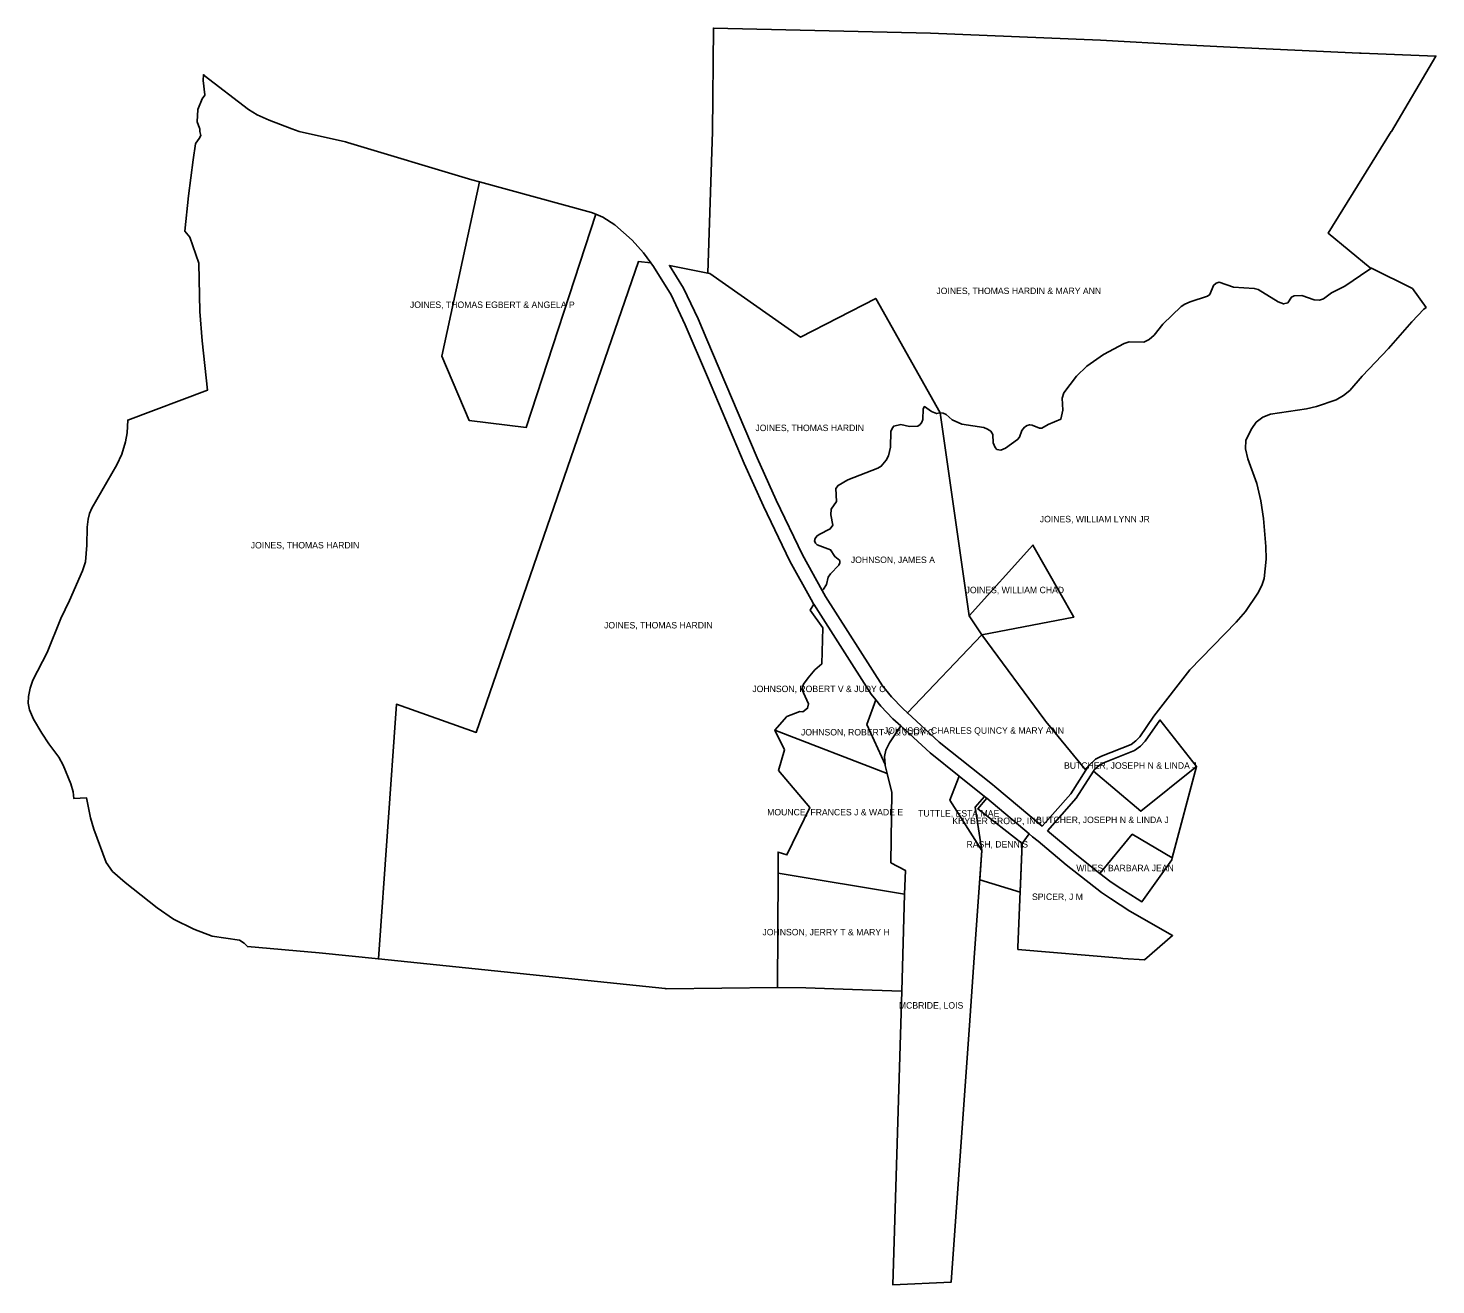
# Model space of a CAD drawing. Extents: x 1390770 to 1396754, y 955095 to 960439.
import ezdxf

# ---------------------------------------------------------------- set-up
doc = ezdxf.new("R2010")
doc.units = 0
doc.layers.add('WILKES_2010PARCELS', color=7, linetype='Continuous')

msp = doc.modelspace()

# ---------------------------------------------------------------- linework, layer by layer
at = {"layer": 'WILKES_2010PARCELS'}
for points in [[(1393678.875, 959999.75), (1393683, 960439.3125), (1394605.75, 960418.125), (1395328, 960388.125), (1395680.375, 960368.9375), (1395879.375, 960358.125), (1396429.75, 960332.8125), (1396436, 960332.5), (1396753.625, 960320.4375), (1396564.5, 960000)], [(1391500.5, 960000), (1391500.5, 960011.5), (1391498, 960014.4375), (1391489.125, 960040.4375), (1391491.5, 960092.8125), (1391509.5, 960139.25), (1391521.125, 960154.4375), (1391520.875, 960156.1875), (1391513.5, 960216.5), (1391515.375, 960241.75), (1391518.875, 960238.3125), (1391707.125, 960093.0625), (1391743.75, 960071), (1391795, 960047.875), (1391890.75, 960011.375), (1391921.5, 960000)], [(1391921.5, 960000), (1392119.375, 959955.625), (1392128.125, 959953), (1392656.125, 959794), (1392688.375, 959785.1875), (1392529.25, 959044.125), (1392645, 958770.1875), (1392886.875, 958740.9375), (1393182.5, 959647.8125), (1393212.75, 959635.4375), (1393264.375, 959602.3125), (1393337.625, 959537.75), (1393385.375, 959483.3125), (1393417.125, 959441), (1393364.5, 959446.25), (1392674.75, 957444.0625), (1392335.875, 957564.125), (1392259, 956480.9375), (1392007.75, 956507), (1391702.5, 956533.875), (1391688.875, 956548.25), (1391667.875, 956560.5), (1391553, 956577.25), (1391475.125, 956607.875), (1391388.5, 956650.5625), (1391318, 956699), (1391182.5, 956805.625), (1391128.75, 956852.875), (1391102.125, 956891.125), (1391049.875, 957032.375), (1391035.625, 957080.875), (1391018.25, 957166), (1390964.75, 957163.25), (1390961.5, 957191.125), (1390952.125, 957225.6875), (1390918.875, 957304.5625), (1390900, 957339.625), (1390858.5, 957396.0625), (1390828.125, 957440.625), (1390793.125, 957501.3125), (1390776, 957539.875), (1390770.25, 957568.5625), (1390771.875, 957597.375), (1390778.875, 957631.9375), (1390789.75, 957666.1875), (1390850.625, 957783.9375), (1390909, 957928.1875), (1390946.625, 958005.6875), (1391001.125, 958132.0625), (1391013.5, 958169.75), (1391019.625, 958241.25), (1391021.75, 958316.6875), (1391024.75, 958351.75), (1391031.25, 958375.25), (1391040.625, 958397.75), (1391147.625, 958582.875), (1391168.875, 958627.8125), (1391184.5, 958679.5), (1391190.625, 958718.25), (1391193.375, 958772.6875), (1391532, 958899.375), (1391510.125, 959109.9375), (1391500.125, 959234.0625), (1391496.125, 959439.875), (1391457.375, 959550), (1391436.5, 959575.625), (1391451.375, 959725.75), (1391472, 959879.8125), (1391481, 959947.5625), (1391482.875, 959950), (1391497.75, 959969.9375), (1391503.75, 959982.75), (1391500.5, 960000)], [(1396564.375, 960000), (1396295.25, 959568.0625), (1396475, 959420.375), (1396479.875, 959418.6875), (1396468.875, 959411.1875), (1396367.375, 959342.25), (1396310.5, 959314.1875), (1396276.75, 959288.5625), (1396259, 959281.8125), (1396236.625, 959283.5), (1396184.125, 959302.1875), (1396150.75, 959301.125), (1396140.125, 959295.4375), (1396124.875, 959271.8125), (1396106.375, 959266.3125), (1396083.75, 959275.875), (1395998.625, 959327.8125), (1395981.5, 959332.25), (1395893.375, 959337.125), (1395832.875, 959358.9375), (1395819.875, 959354.4375), (1395808.875, 959345.4375), (1395792.875, 959306.625), (1395783.75, 959299.25), (1395710, 959275.375), (1395686.75, 959266.1875), (1395671.25, 959256), (1395593.5, 959179.875), (1395556.25, 959134.125), (1395534.625, 959114.5625), (1395513.125, 959104.1875), (1395450, 959105.375), (1395429.375, 959098.0625), (1395341.5, 959051.4375), (1395269.625, 959001.3125), (1395226.25, 958959.75), (1395172.125, 958887.9375), (1395165.375, 958865.3125), (1395168.25, 958814.4375), (1395160.25, 958776.9375), (1395106.25, 958754.4375), (1395079, 958737.625), (1395068.375, 958737.5625), (1395038.25, 958750.4375), (1395027.125, 958752.4375), (1395015.875, 958749.625), (1395005.625, 958742.9375), (1394994.5, 958728.125), (1394983.5, 958699.25), (1394976.125, 958689.9375), (1394924.5, 958653.6875), (1394905.125, 958644.25), (1394887.75, 958647.6875), (1394879.875, 958656.25), (1394871.75, 958675.625), (1394870.5, 958711.3125), (1394862.125, 958725), (1394848.625, 958734.5625), (1394832.5, 958740.875), (1394738.875, 958754.875), (1394698.25, 958774.0625), (1394671.875, 958796.6875), (1394659.625, 958802.0625), (1394646.5, 958803.25), (1394372.75, 959290.1875), (1394052.75, 959125.375), (1393667.75, 959396.1875), (1393659.625, 959397.8125), (1393678.875, 960000)]]:
    msp.add_lwpolyline(points, dxfattribs=at)
for points in [[(1392529.25, 959044.125), (1392688.375, 959785.1875), (1393164.625, 959655.125), (1393182.5, 959647.8125), (1392886.875, 958740.9375), (1392645, 958770.1875)], [(1392674.75, 957444.0625), (1393364.5, 959446.25), (1393417.125, 959441), (1393428.25, 959426.125), (1393503.125, 959305.375), (1393563.25, 959178.25), (1393657.25, 958956.9375), (1393814, 958587.75), (1393895.375, 958406.125), (1394008, 958172.4375), (1394098.875, 958009.0625), (1394108.5, 957991.625), (1394109.875, 957989.375), (1394094.5, 957963.5625), (1394148, 957889.5625), (1394143.25, 957735.5625), (1394114, 957710.375), (1394085.25, 957676), (1394066.5, 957648.8125), (1394058.5, 957628), (1394086.875, 957565.625), (1394083.25, 957547.1875), (1394063.25, 957531.1875), (1394049.625, 957533.1875), (1393995.25, 957512), (1393944, 957454.4375), (1393984.875, 957370.8125), (1393960, 957282.0625), (1394092.5, 957125.25), (1393995.625, 956923.25), (1393958, 956935.25), (1393957.5, 956845.75), (1393954.875, 956358.9375), (1393482.5, 956354.1875), (1393478.25, 956354.625), (1392259, 956480.9375), (1392335.875, 957564.125)], [(1394145.5, 958048.5), (1394061.25, 958200.0625), (1393949.875, 958431.375), (1393869, 958611.75), (1393655.25, 959115.1875), (1393618, 959202.875), (1393555.875, 959334.125), (1393496.125, 959430.3125), (1393659.625, 959397.8125), (1393667.75, 959396.1875), (1394052.75, 959125.375), (1394372.75, 959290.1875), (1394646.5, 958803.25), (1394631.625, 958800.0625), (1394610, 958808.75), (1394579.5, 958829.6875), (1394574.625, 958820.5), (1394572.375, 958775.25), (1394569.125, 958763.0625), (1394561.625, 958753.375), (1394551.625, 958746.875), (1394516.25, 958745.4375), (1394479.25, 958753.0625), (1394449.625, 958746.875), (1394444.25, 958740.125), (1394437.625, 958724.0625), (1394436, 958657.25), (1394427.625, 958620.4375), (1394417.5, 958602.5625), (1394396.375, 958576.375), (1394382.375, 958567.375), (1394254.375, 958518), (1394212.5, 958494.5625), (1394203.5, 958481.5625), (1394206.375, 958425.9375), (1394184, 958393.125), (1394182.375, 958369.875), (1394190.375, 958325.125), (1394179.375, 958309.375), (1394132.75, 958285.875), (1394122.375, 958278.9375), (1394115, 958269.5), (1394112.75, 958259.125), (1394116.375, 958249.625), (1394124, 958241.4375), (1394180.75, 958220.3125), (1394198.375, 958191.875), (1394219.75, 958175.125), (1394219.875, 958166.125), (1394215.5, 958155.625), (1394181.25, 958118.875), (1394171, 958103.875), (1394163.5, 958073.6875), (1394150.75, 958053.4375)], [(1394769.5, 957939.6875), (1394646.5, 958803.25), (1394659.625, 958802.0625), (1394671.875, 958796.6875), (1394698.25, 958774.0625), (1394738.875, 958754.875), (1394832.5, 958740.875), (1394848.625, 958734.5625), (1394862.125, 958725), (1394870.5, 958711.3125), (1394871.75, 958675.625), (1394879.875, 958656.25), (1394887.75, 958647.6875), (1394905.125, 958644.25), (1394924.5, 958653.6875), (1394976.125, 958689.9375), (1394983.5, 958699.25), (1394994.5, 958728.125), (1395005.625, 958742.9375), (1395015.875, 958749.625), (1395027.125, 958752.4375), (1395038.25, 958750.4375), (1395068.375, 958737.5625), (1395079, 958737.625), (1395106.25, 958754.4375), (1395160.25, 958776.9375), (1395168.25, 958814.4375), (1395165.375, 958865.3125), (1395172.125, 958887.9375), (1395226.25, 958959.75), (1395269.625, 959001.3125), (1395341.5, 959051.4375), (1395429.375, 959098.0625), (1395450, 959105.375), (1395513.125, 959104.1875), (1395534.625, 959114.5625), (1395556.25, 959134.125), (1395593.5, 959179.875), (1395671.25, 959256), (1395686.75, 959266.1875), (1395710, 959275.375), (1395783.75, 959299.25), (1395792.875, 959306.625), (1395808.875, 959345.4375), (1395819.875, 959354.4375), (1395832.875, 959358.9375), (1395893.375, 959337.125), (1395981.5, 959332.25), (1395998.625, 959327.8125), (1396083.75, 959275.875), (1396106.375, 959266.3125), (1396124.875, 959271.8125), (1396140.125, 959295.4375), (1396150.75, 959301.125), (1396184.125, 959302.1875), (1396236.625, 959283.5), (1396259, 959281.8125), (1396276.75, 959288.5625), (1396310.5, 959314.1875), (1396367.375, 959342.25), (1396468.875, 959411.1875), (1396479.875, 959418.6875), (1396654.125, 959332.3125), (1396712.125, 959251.4375), (1396703, 959244.6875), (1396651.5, 959190.6875), (1396552.375, 959076.875), (1396439.875, 958959.25), (1396387.5, 958898.75), (1396361.625, 958876.8125), (1396330.375, 958858.25), (1396246.125, 958829.6875), (1396203.75, 958820.25), (1396050.75, 958797.75), (1396018.625, 958784.625), (1395990.375, 958763.0625), (1395971.25, 958737.4375), (1395946.5, 958687.625), (1395944, 958650.125), (1395955.125, 958607.4375), (1395993.25, 958502.5625), (1396009.125, 958429.8125), (1396020.375, 958353.375), (1396031.125, 958234.6875), (1396032, 958180.5625), (1396023.375, 958098.1875), (1396013.875, 958069.0625), (1395997, 958037.125), (1395944, 957958.75), (1395904.875, 957913.5625), (1395708.5, 957710.5625), (1395555.5, 957514.125), (1395495, 957425.6875), (1395477.875, 957408.125), (1395458.125, 957393.3125), (1395332.625, 957343.0625), (1395307.125, 957330.0625), (1395278.375, 957304), (1395266, 957284.4375), (1395096, 957491.375), (1395091.75, 957496.5), (1394823.625, 957858.9375), (1395214.875, 957934.375), (1395040.75, 958241.0625)], [(1394145.5, 958048.5), (1394150.75, 958053.4375), (1394163.5, 958073.6875), (1394171, 958103.875), (1394181.25, 958118.875), (1394215.5, 958155.625), (1394219.875, 958166.125), (1394219.75, 958175.125), (1394198.375, 958191.875), (1394180.75, 958220.3125), (1394124, 958241.4375), (1394116.375, 958249.625), (1394112.75, 958259.125), (1394115, 958269.5), (1394122.375, 958278.9375), (1394132.75, 958285.875), (1394179.375, 958309.375), (1394190.375, 958325.125), (1394182.375, 958369.875), (1394184, 958393.125), (1394206.375, 958425.9375), (1394203.5, 958481.5625), (1394212.5, 958494.5625), (1394254.375, 958518), (1394382.375, 958567.375), (1394396.375, 958576.375), (1394417.5, 958602.5625), (1394427.625, 958620.4375), (1394436, 958657.25), (1394437.625, 958724.0625), (1394444.25, 958740.125), (1394449.625, 958746.875), (1394479.25, 958753.0625), (1394516.25, 958745.4375), (1394551.625, 958746.875), (1394561.625, 958753.375), (1394569.125, 958763.0625), (1394572.375, 958775.25), (1394574.625, 958820.5), (1394579.5, 958829.6875), (1394610, 958808.75), (1394631.625, 958800.0625), (1394646.5, 958803.25), (1394769.5, 957939.6875), (1394823.625, 957858.9375), (1394507.75, 957527.0625), (1394487.875, 957545.375), (1394439.75, 957596.0625), (1394401.625, 957642.25), (1394160, 958022.25)], [(1394769.5, 957939.6875), (1395040.75, 958241.0625), (1395214.875, 957934.375), (1394823.625, 957858.9375)], [(1393944, 957454.4375), (1393995.25, 957512), (1394049.625, 957533.1875), (1394063.25, 957531.1875), (1394083.25, 957547.1875), (1394086.875, 957565.625), (1394058.5, 957628), (1394066.5, 957648.8125), (1394085.25, 957676), (1394114, 957710.375), (1394143.25, 957735.5625), (1394148, 957889.5625), (1394094.5, 957963.5625), (1394109.875, 957989.375), (1394352.875, 957606.875), (1394372.625, 957582.9375), (1394334.625, 957478), (1394413, 957307.3125), (1394413.25, 957304.0625), (1394421.875, 957269.5)], [(1394868.75, 957222.625), (1394643, 957402.625), (1394507.75, 957527.0625), (1394823.625, 957858.9375), (1395091.75, 957496.5), (1395096, 957491.375), (1395266, 957284.4375), (1395201.5, 957182.6875), (1395079.75, 957045.6875), (1394879, 957214.4375)], [(1394413, 957307.3125), (1394334.625, 957478), (1394372.625, 957582.9375), (1394394.75, 957556.3125), (1394445.625, 957502.625), (1394479, 957472), (1394432, 957400.4375), (1394416, 957368.8125), (1394410.75, 957341.25)], [(1394483.25, 956344.25), (1394495.75, 956755.75), (1394498.75, 956857.25), (1394437.625, 956890.0625), (1394442, 957188.4375), (1394421.875, 957269.5), (1394413.25, 957304.0625), (1394413, 957307.3125), (1394410.75, 957341.25), (1394416, 957368.8125), (1394432, 957400.4375), (1394479, 957472), (1394604, 957357), (1394728.125, 957258.0625), (1394688.25, 957155.5), (1394824.25, 956942.25), (1394793.375, 956507.25), (1394772.75, 956218.625), (1394693.75, 955106.5), (1394445.625, 955095)], [(1395298, 957278.875), (1395301.625, 957284.5), (1395324.375, 957305.1875), (1395345.125, 957315.6875), (1395472.875, 957366.9375), (1395497.875, 957385.5), (1395518.25, 957406.6875), (1395579.75, 957496.375), (1395580.875, 957497.8125), (1395736.375, 957300.0625), (1395499.875, 957109.1875)], [(1393957.5, 956845.75), (1393958, 956935.25), (1393995.625, 956923.25), (1394092.5, 957125.25), (1393960, 957282.0625), (1393984.875, 957370.8125), (1393944, 957454.4375), (1394421.875, 957269.5), (1394442, 957188.4375), (1394437.625, 956890.0625), (1394498.75, 956857.25), (1394495.75, 956755.75)], [(1395102.625, 957026.375), (1395225.5, 957164.5625), (1395298, 957278.875), (1395499.875, 957109.1875), (1395736.375, 957300.0625), (1395632.75, 956910.5), (1395463.125, 957011.1875), (1395325.75, 956844.875), (1395220.5, 956927.3125)], [(1394688.25, 957155.5), (1394728.125, 957258.0625), (1394835.5, 957172.4375), (1394795.25, 957125.875), (1394824.25, 956942.25)], [(1394815.375, 956817.1875), (1394824.25, 956942.25), (1394795.25, 957125.875), (1394835.5, 957172.4375), (1394841, 957168.0625), (1394845.125, 957164.5625), (1394806.875, 957118.8125), (1394995.25, 956971.25), (1394986.875, 956764.75)], [(1394995.25, 956971.25), (1394806.875, 957118.8125), (1394845.125, 957164.5625), (1395024.875, 957013.5)], [(1394976.75, 956520.9375), (1394977.375, 956530.625), (1394995.25, 956971.25), (1395024.875, 957013.5), (1395039.875, 957000.875), (1395062.875, 956981.5625), (1395182.75, 956880.6875), (1395332.125, 956763.6875), (1395370.125, 956737.375), (1395452.875, 956684.5625), (1395634.5, 956580.5625), (1395515.625, 956477.5625), (1395423.125, 956483.4375), (1395414.625, 956484.1875)], [(1395325.75, 956844.875), (1395463.125, 957011.1875), (1395632.75, 956910.5), (1395630.75, 956903.125), (1395504.375, 956724.1875), (1395483.875, 956735.9375), (1395403.375, 956787.375), (1395367.625, 956812.0625)], [(1393954.875, 956358.9375), (1393957.5, 956845.75), (1394495.75, 956755.75), (1394483.25, 956344.25), (1394274.75, 956351.25), (1394075.25, 956358.125)]]:
    msp.add_lwpolyline(points, close=True, dxfattribs=at)

# ---------------------------------------------------------------- texts
for s, p in [('JOINES, THOMAS HARDIN & MARY ANN', (1394630.728837, 959308.384504)), ('JOINES, THOMAS EGBERT & ANGELA P', (1392393.004633, 959249.322004)), ('JOINES, THOMAS HARDIN', (1393861.436894, 958725.665754)), ('JOINES, WILLIAM LYNN JR', (1395070.266574, 958337.822004)), ('JOINES, THOMAS HARDIN', (1391716.394627, 958226.728254)), ('JOHNSON, JAMES A', (1394267.155267, 958164.634504)), ('JOINES, WILLIAM CHAD', (1394754.807592, 958036.259504)), ('JOINES, THOMAS HARDIN', (1393218.155742, 957886.478254)), ('JOHNSON, ROBERT V & JUDY C', (1393848.414216, 957615.697004)), ('JOHNSON, CHARLES QUINCY & MARY ANN', (1394407.396268, 957438.572004)), ('JOHNSON, ROBERT V & JUDY C', (1394055.152172, 957431.384504)), ('BUTCHER, JOSEPH N & LINDA J', (1395173.132784, 957289.759504)), ('MOUNCE, FRANCES J & WADE E', (1393911.423068, 957091.353254)), ('TUTTLE, ESTA MAE', (1394553.03108, 957086.415754)), ('KHYBER GROUP, INC', (1394698.440909, 957054.165754)), ('BUTCHER, JOSEPH N & LINDA J', (1395054.759877, 957058.728254)), ('RASH, DENNIS', (1394758.76052, 956954.853254)), ('WILES, BARBARA JEAN', (1395225.538706, 956853.947004)), ('SPICER, J M', (1395037.104665, 956731.790754)), ('JOHNSON, JERRY T & MARY H', (1393891.445439, 956581.259504)), ('MCBRIDE, LOIS', (1394471.387427, 956269.759504))]:
    msp.add_text(s, height=27.480992, dxfattribs=at).set_placement(p)

doc.saveas('drawing.dxf')
